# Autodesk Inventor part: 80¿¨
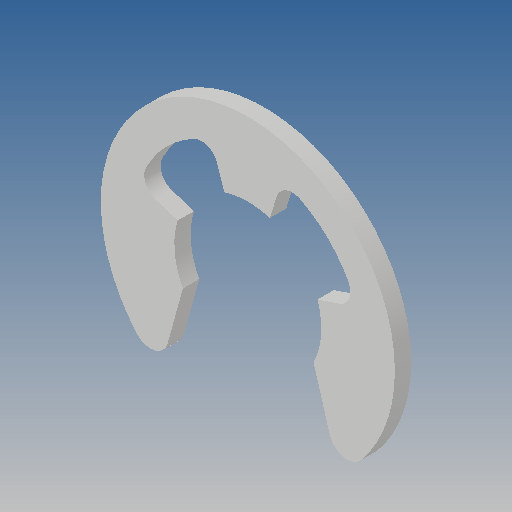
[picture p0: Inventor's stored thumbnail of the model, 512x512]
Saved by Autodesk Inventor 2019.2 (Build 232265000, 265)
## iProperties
Created: 2013-07
Part Number: 80¿¨
Material: Ogólny
Document SubType Name: Modeling
Designer: CADENGINEERING4
Density: 1 g/cm^3
Appearance: Domyślna
Author: CADENGINEERING4
Revision Number: ÈÎºÎ
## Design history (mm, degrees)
feature "Í¹Ì¨-À­Éì1"
node "Bryła1"
